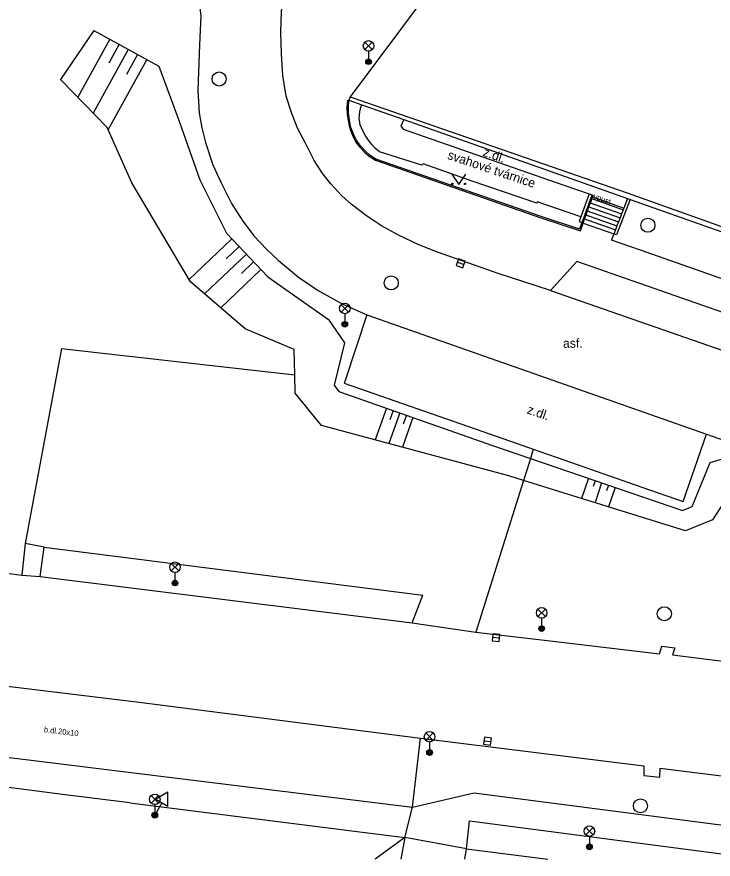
# Model space of a CAD drawing. Extents: x -598932 to -598196, y -1162207 to -1161504.
# Drawn here: x -598771.5 to -598721.9, y -1162207 to -1162147.1 of the extents above; entities that cross this region are included whole.
import ezdxf

# ---------------------------------------------------------------- set-up
doc = ezdxf.new("R2010")
doc.units = 0
for name, color, linetype in [('kanalizace - povrch.  znaky - skut. velikost', 7, 'Continuous'), ('Level 27', 7, 'Continuous'), ('Level 33', 7, 'Continuous'), ('Level 34', 7, 'Continuous'), ('Level 36', 7, 'Continuous'), ('specificka linie pasportu komunikaci', 7, 'Continuous'), ('TM - budovy zdene_ betonove - VP', 7, 'Continuous'), ('TM - chodniky - VP', 7, 'Continuous'), ('TM - dolni hrana svahu', 7, 'Continuous'), ('TM - horni hrana svahu', 7, 'Continuous'), ('TM - komunikace - VP', 7, 'Continuous'), ('TM - pomocna konstrukcna linie', 7, 'Continuous'), ('TM - popis povrchu', 7, 'Continuous'), ('TM - poznamka', 7, 'Continuous'), ('TM - rozhrani mezi zpev. plochami mezi sebou - VP', 7, 'Continuous'), ('TM - rozhrani ploch obecne - VP', 7, 'Continuous'), ('TM - schody - VP', 7, 'Continuous'), ('TM - srafovani', 7, 'Continuous'), ('TM - zabradli - VP', 7, 'Continuous')]:
    doc.layers.add(name, color=color, linetype=linetype)

msp = doc.modelspace()

# ---------------------------------------------------------------- linework, layer by layer
at = {"layer": 'kanalizace - povrch.  znaky - skut. velikost'}
for points in [[(-598730.65, -1162159.96), (-598728.35, -1162160.79)], [(-598730.61, -1162159.84), (-598730.52, -1162159.87)], [(-598730.52, -1162159.87), (-598728.31, -1162160.67)]]:
    msp.add_lwpolyline(points, dxfattribs=at)
at = {"layer": 'Level 27'}
for p, q in [((-598740.136, -1162164.518), (-598739.664, -1162164.682)), ((-598737.649, -1162191.185), (-598737.151, -1162191.235)), ((-598738.249, -1162198.545), (-598737.751, -1162198.595))]:
    msp.add_line(p, q, dxfattribs=at)
for points in [[(-598740.218, -1162164.754), (-598739.746, -1162164.918), (-598739.582, -1162164.446), (-598740.054, -1162164.282)], [(-598737.674, -1162191.433), (-598737.177, -1162191.484), (-598737.126, -1162190.987), (-598737.623, -1162190.936)], [(-598738.274, -1162198.793), (-598737.777, -1162198.844), (-598737.726, -1162198.347), (-598738.223, -1162198.296)]]:
    msp.add_lwpolyline(points, close=True, dxfattribs=at)
for centre in [(-598757.09, -1162151.49), (-598726.59, -1162161.89), (-598744.85, -1162165.99), (-598725.42, -1162189.51), (-598727.12, -1162203.17)]:
    msp.add_circle(centre, 0.5, dxfattribs=at)
at = {"layer": 'Level 33'}
for p, q in [((-598746.725, -1162149.4), (-598746.195, -1162148.87)), ((-598746.725, -1162148.87), (-598746.195, -1162149.4)), ((-598746.46, -1162149.51), (-598746.46, -1162150.26)), ((-598748.415, -1162168.07), (-598747.885, -1162167.54)), ((-598748.415, -1162167.54), (-598747.885, -1162168.07)), ((-598748.15, -1162168.18), (-598748.15, -1162168.93)), ((-598760.495, -1162186.47), (-598759.965, -1162185.94)), ((-598760.495, -1162185.94), (-598759.965, -1162186.47)), ((-598760.23, -1162186.58), (-598760.23, -1162187.33)), ((-598734.415, -1162189.71), (-598733.885, -1162189.18)), ((-598734.415, -1162189.18), (-598733.885, -1162189.71)), ((-598734.15, -1162189.82), (-598734.15, -1162190.57)), ((-598742.385, -1162198.52), (-598741.855, -1162197.99)), ((-598742.385, -1162197.99), (-598741.855, -1162198.52)), ((-598742.12, -1162198.63), (-598742.12, -1162199.38)), ((-598761.935, -1162202.97), (-598761.405, -1162202.44)), ((-598761.935, -1162202.44), (-598761.405, -1162202.97)), ((-598761.67, -1162203.08), (-598761.67, -1162203.83)), ((-598731.015, -1162205.23), (-598730.485, -1162204.7)), ((-598731.015, -1162204.7), (-598730.485, -1162205.23)), ((-598730.75, -1162205.34), (-598730.75, -1162206.09))]:
    msp.add_line(p, q, dxfattribs=at)
for centre, radius in [((-598746.46, -1162149.135), 0.375), ((-598746.46, -1162150.26), 0.2), ((-598746.46, -1162150.26), 0.145), ((-598746.46, -1162150.26), 0.0876), ((-598748.15, -1162167.805), 0.375), ((-598748.15, -1162168.93), 0.2), ((-598748.15, -1162168.93), 0.145), ((-598748.15, -1162168.93), 0.0876), ((-598760.23, -1162186.205), 0.375), ((-598760.23, -1162187.33), 0.2), ((-598760.23, -1162187.33), 0.145), ((-598760.23, -1162187.33), 0.0876), ((-598734.15, -1162189.445), 0.375), ((-598734.15, -1162190.57), 0.2), ((-598734.15, -1162190.57), 0.145), ((-598734.15, -1162190.57), 0.0876), ((-598742.12, -1162198.255), 0.375), ((-598742.12, -1162199.38), 0.2), ((-598742.12, -1162199.38), 0.145), ((-598742.12, -1162199.38), 0.0876), ((-598761.67, -1162202.705), 0.375), ((-598761.67, -1162203.83), 0.2), ((-598761.67, -1162203.83), 0.145), ((-598761.67, -1162203.83), 0.0876), ((-598730.75, -1162204.965), 0.375), ((-598730.75, -1162206.09), 0.2), ((-598730.75, -1162206.09), 0.145), ((-598730.75, -1162206.09), 0.0876)]:
    msp.add_circle(centre, radius, dxfattribs=at)
at = {"layer": 'Level 34'}
for p, q in [((-598761.163, -1162202.947), (-598761.67, -1162203.83)), ((-598761.887, -1162203.706), (-598761.453, -1162203.954))]:
    msp.add_line(p, q, dxfattribs=at)
msp.add_lwpolyline([(-598761.597, -1162202.698), (-598760.73, -1162203.196), (-598760.732, -1162202.196)], close=True, dxfattribs=at)
at = {"layer": 'Level 36'}
msp.add_lwpolyline([(-598740.54, -1162158.25), (-598740.04, -1162159), (-598739.54, -1162158.25)], dxfattribs=at)
for centre in [(-598740.49, -1162158.95), (-598739.591, -1162158.95)]:
    msp.add_circle(centre, 0.05, dxfattribs=at)
at = {"layer": 'specificka linie pasportu komunikaci'}
for points in [[(-598768.31, -1162170.66), (-598770.88, -1162184.51)], [(-598768.31, -1162170.66), (-598751.7, -1162172.52)], [(-598734.74, -1162177.81), (-598734.95, -1162178.48)], [(-598734.95, -1162178.48), (-598735.02, -1162178.72), (-598735.43, -1162180.03), (-598738.82, -1162190.81)], [(-598770.88, -1162184.51), (-598771.12, -1162186.77)], [(-598769.53, -1162184.78), (-598770.88, -1162184.51)], [(-598769.83, -1162186.86), (-598769.53, -1162184.78)], [(-598769.53, -1162184.78), (-598742.6, -1162188.19)], [(-598743.36, -1162190.15), (-598742.6, -1162188.19)], [(-598743.88, -1162205.42), (-598743.34, -1162203.26)], [(-598743.88, -1162205.42), (-598744.16, -1162206.96)], [(-598739.5, -1162206.22), (-598743.88, -1162205.42)]]:
    msp.add_lwpolyline(points, dxfattribs=at)
at = {"layer": 'TM - budovy zdene_ betonove - VP'}
for points in [[(-598728.07, -1162159.58), (-598700.55, -1162169.39), (-598688.31, -1162134.81)], [(-598733.44, -1162140.3), (-598735.12, -1162145.09), (-598740.6, -1162143.17), (-598747.78, -1162152.76)], [(-598747.78, -1162152.76), (-598728.07, -1162159.58)], [(-598739.603, -1162206.96), (-598739.5, -1162206.22)], [(-598739.5, -1162206.22), (-598733.697, -1162206.96)]]:
    msp.add_lwpolyline(points, dxfattribs=at)
at = {"layer": 'TM - chodniky - VP'}
for points in [[(-598731.28, -1162161.7), (-598731.45, -1162162.16), (-598734.18, -1162161.26), (-598745.94, -1162157.18), (-598746.36, -1162156.9), (-598746.73, -1162156.58), (-598747.05, -1162156.22), (-598747.31, -1162155.85), (-598747.53, -1162155.41), (-598747.71, -1162154.94), (-598747.82, -1162154.41), (-598747.88, -1162153.92), (-598747.89, -1162153.49), (-598747.86, -1162153)], [(-598747.78, -1162152.76), (-598747.86, -1162153)], [(-598747.86, -1162153), (-598746.94, -1162153.32)], [(-598731.35, -1162161.29), (-598734.47, -1162160.22), (-598734.5, -1162160.32), (-598739.16, -1162158.74), (-598742.57, -1162157.53), (-598742.68, -1162157.61), (-598745.69, -1162156.67), (-598745.96, -1162156.43), (-598746.24, -1162156.13), (-598746.52, -1162155.77), (-598746.71, -1162155.48), (-598746.87, -1162155.17), (-598747.05, -1162154.75), (-598747.12, -1162154.28), (-598747.08, -1162153.83), (-598746.98, -1162153.43), (-598746.94, -1162153.32)], [(-598746.94, -1162153.32), (-598743.94, -1162154.38)], [(-598743.94, -1162154.38), (-598728.04, -1162159.99)], [(-598728.04, -1162159.99), (-598728.31, -1162160.67)], [(-598728.04, -1162159.99), (-598727.85, -1162160.06)], [(-598727.85, -1162160.06), (-598710.85, -1162166.05)], [(-598728.35, -1162160.79), (-598728.46, -1162161.07)], [(-598728.31, -1162160.67), (-598728.35, -1162160.79)], [(-598731.35, -1162161.29), (-598731.47, -1162161.63), (-598731.28, -1162161.7)], [(-598728.57, -1162161.35), (-598728.68, -1162161.64)], [(-598728.46, -1162161.07), (-598728.57, -1162161.35)], [(-598728.79, -1162161.92), (-598728.9, -1162162.21)], [(-598728.68, -1162161.64), (-598728.79, -1162161.92)], [(-598729.01, -1162162.49), (-598729.18, -1162162.96)], [(-598728.9, -1162162.21), (-598729.01, -1162162.49)], [(-598710.85, -1162166.05), (-598711.92, -1162168.97), (-598717.68, -1162166.98), (-598727.11, -1162163.67), (-598729.18, -1162162.96)], [(-598763.45, -1162202.95), (-598768.41, -1162202.34), (-598772.43, -1162201.81)], [(-598743.34, -1162203.26), (-598738.95, -1162202.25)], [(-598738.95, -1162202.25), (-598702.604, -1162206.96)], [(-598763.45, -1162202.95), (-598743.88, -1162205.42)], [(-598739.5, -1162206.22), (-598739.28, -1162204.23), (-598718.442, -1162206.96)], [(-598743.88, -1162205.42), (-598745.996, -1162206.96)]]:
    msp.add_lwpolyline(points, dxfattribs=at)
at = {"layer": 'TM - dolni hrana svahu'}
msp.add_lwpolyline([(-598710.29, -1162184.81), (-598711.52, -1162182.65), (-598720.39, -1162180.35), (-598722, -1162182.84), (-598723.92, -1162183.61), (-598735.43, -1162180.03), (-598736.48, -1162179.7), (-598749.81, -1162176.12), (-598751.67, -1162173.82), (-598751.7, -1162172.52), (-598751.75, -1162170.72), (-598755.24, -1162169.25), (-598759.12, -1162165.91), (-598763.29, -1162158.88), (-598765.05, -1162154.94), (-598768.37, -1162151.53)], dxfattribs=at)
at = {"layer": 'TM - horni hrana svahu'}
for points in [[(-598766.01, -1162148.03), (-598761.39, -1162150.58), (-598759.9, -1162154.57), (-598758.47, -1162158.67), (-598756.57, -1162162.45), (-598753.63, -1162165.56), (-598749.3, -1162168.58), (-598748.17, -1162170.26), (-598748.9, -1162173.26), (-598748.58, -1162173.7), (-598737.64, -1162177.56), (-598734.95, -1162178.48)], [(-598734.95, -1162178.48), (-598724.14, -1162182.16), (-598723.43, -1162181.89), (-598722.15, -1162178.76), (-598720.89, -1162178.38), (-598710.84, -1162181.96), (-598710.29, -1162184.81)]]:
    msp.add_lwpolyline(points, dxfattribs=at)
at = {"layer": 'TM - komunikace - VP'}
for points in [[(-598758.64, -1162145.01), (-598758.55, -1162145.7), (-598758.4, -1162147), (-598758.48, -1162149.06), (-598758.61, -1162152.3), (-598758.5, -1162153.9), (-598758.32, -1162154.95), (-598758.07, -1162156.01), (-598757.54, -1162157.59), (-598756.98, -1162158.83), (-598756.22, -1162160.34), (-598755.4, -1162161.6), (-598754.59, -1162162.66), (-598753.75, -1162163.57), (-598752.86, -1162164.4), (-598751.44, -1162165.58), (-598750.04, -1162166.52), (-598748.33, -1162167.48), (-598746.58, -1162168.25)], [(-598737.25, -1162165.31), (-598741.56, -1162163.8), (-598742.89, -1162163.28), (-598744.33, -1162162.6), (-598745.53, -1162161.92), (-598746.6, -1162161.21), (-598747.7, -1162160.38), (-598748.35, -1162159.79), (-598749.15, -1162158.95), (-598749.72, -1162158.23), (-598750.32, -1162157.29), (-598750.93, -1162156.1), (-598751.51, -1162154.98), (-598751.93, -1162153.94), (-598752.31, -1162152.7), (-598752.55, -1162151.24), (-598752.65, -1162149.69), (-598752.71, -1162148.15), (-598752.66, -1162146.7), (-598752.54, -1162145.66)], [(-598704.24, -1162176.69), (-598704.55, -1162173.89), (-598704.6, -1162173.87), (-598711, -1162171.65), (-598718.19, -1162169.15), (-598731.64, -1162164.47), (-598733.52, -1162166.53)], [(-598733.52, -1162166.53), (-598737.25, -1162165.31)], [(-598746.58, -1162168.25), (-598748.13, -1162172.92), (-598748.2, -1162173.12), (-598738.88, -1162176.37), (-598737.45, -1162176.87), (-598735.9, -1162177.41), (-598734.74, -1162177.81), (-598732.58, -1162178.56), (-598727.02, -1162180.5), (-598724.08, -1162181.52), (-598722.41, -1162176.74)], [(-598722.41, -1162176.74), (-598712.86, -1162180.1)], [(-598772.19, -1162186.63), (-598771.12, -1162186.77), (-598769.83, -1162186.86), (-598743.36, -1162190.15)], [(-598743.36, -1162190.15), (-598738.82, -1162190.81), (-598733.14, -1162191.48)], [(-598733.14, -1162191.48), (-598725.77, -1162192.35), (-598725.6, -1162191.81), (-598724.67, -1162191.93), (-598724.84, -1162192.43), (-598699.38, -1162195.64), (-598688.04, -1162197.08), (-598673.19, -1162198.97)], [(-598743.34, -1162203.26), (-598742.76, -1162198.35)], [(-598742.76, -1162198.35), (-598737.22, -1162199.04)], [(-598737.22, -1162199.04), (-598726.89, -1162200.32), (-598726.88, -1162201.01), (-598725.74, -1162201.14), (-598725.72, -1162200.49), (-598689.52, -1162205.02), (-598681.7, -1162206)], [(-598773.38, -1162199.57), (-598743.34, -1162203.26)]]:
    msp.add_lwpolyline(points, dxfattribs=at)
at = {"layer": 'TM - pomocna konstrukcna linie'}
msp.add_lwpolyline([(-598766.01, -1162148.03), (-598768.37, -1162151.53)], dxfattribs=at)
at = {"layer": 'TM - rozhrani mezi zpev. plochami mezi sebou - VP'}
for points in [[(-598772.77, -1162194.58), (-598762.79, -1162195.8)], [(-598762.79, -1162195.8), (-598742.76, -1162198.35)]]:
    msp.add_lwpolyline(points, dxfattribs=at)
at = {"layer": 'TM - rozhrani ploch obecne - VP'}
for points in [[(-598743.94, -1162154.38), (-598744.16, -1162154.84), (-598744.01, -1162155.05), (-598732.58, -1162159.03), (-598730.76, -1162159.66), (-598730.569, -1162159.726)], [(-598730.76, -1162159.66), (-598731.35, -1162161.29)], [(-598730.76, -1162160.26), (-598730.87, -1162160.55)], [(-598730.65, -1162159.96), (-598730.76, -1162160.26)], [(-598730.76, -1162160.26), (-598728.46, -1162161.07)], [(-598730.61, -1162159.84), (-598730.65, -1162159.96)], [(-598730.569, -1162159.726), (-598730.61, -1162159.84)], [(-598727.85, -1162160.06), (-598728.82, -1162162.56), (-598729.01, -1162162.49)], [(-598730.97, -1162160.83), (-598731.07, -1162161.12)], [(-598730.87, -1162160.55), (-598730.97, -1162160.83)], [(-598731.18, -1162161.41), (-598731.28, -1162161.7)], [(-598731.07, -1162161.12), (-598731.18, -1162161.41)], [(-598731.28, -1162161.7), (-598731.19, -1162161.73)], [(-598731.19, -1162161.73), (-598729.01, -1162162.49)], [(-598733.52, -1162166.53), (-598712.19, -1162173.94), (-598704.24, -1162176.69)], [(-598746.58, -1162168.25), (-598722.41, -1162176.74)]]:
    msp.add_lwpolyline(points, dxfattribs=at)
at = {"layer": 'TM - schody - VP'}
for points in [[(-598730.97, -1162160.83), (-598728.68, -1162161.64)], [(-598730.87, -1162160.55), (-598728.57, -1162161.35)], [(-598731.18, -1162161.41), (-598728.9, -1162162.21)], [(-598731.07, -1162161.12), (-598728.79, -1162161.92)]]:
    msp.add_lwpolyline(points, dxfattribs=at)
at = {"layer": 'TM - srafovani'}
for points in [[(-598764.86, -1162148.66), (-598767.14, -1162152.79)], [(-598763.55, -1162149.39), (-598766.05, -1162153.92)], [(-598764.92, -1162150.33), (-598764.2, -1162149.03)], [(-598762.89, -1162149.75), (-598763.67, -1162151.17)], [(-598762.23, -1162150.11), (-598764.98, -1162155.09)], [(-598756.18, -1162162.86), (-598759.22, -1162165.74)], [(-598755.67, -1162163.41), (-598756.58, -1162164.27)], [(-598755.15, -1162163.95), (-598758.13, -1162166.76)], [(-598754.12, -1162165.04), (-598756.98, -1162167.75)], [(-598754.64, -1162164.5), (-598755.51, -1162165.32)], [(-598745.18, -1162174.9), (-598745.98, -1162177.15)], [(-598744.24, -1162175.23), (-598745.01, -1162177.41)], [(-598744.71, -1162175.07), (-598744.95, -1162175.73)], [(-598743.3, -1162175.56), (-598744.04, -1162177.67)], [(-598743.77, -1162175.4), (-598744, -1162176.04)], [(-598730.82, -1162179.88), (-598731.31, -1162181.31)], [(-598730.35, -1162180.05), (-598730.49, -1162180.47)], [(-598729.88, -1162180.21), (-598730.35, -1162181.61)], [(-598729.4, -1162180.37), (-598729.54, -1162180.78)], [(-598728.93, -1162180.53), (-598729.4, -1162181.91)]]:
    msp.add_lwpolyline(points, dxfattribs=at)
at = {"layer": 'TM - zabradli - VP'}
for points in [[(-598747.96, -1162152.99), (-598748, -1162153.51), (-598747.98, -1162154.01), (-598747.92, -1162154.42), (-598747.84, -1162154.83), (-598747.72, -1162155.21), (-598747.55, -1162155.61), (-598747.31, -1162156.04), (-598747.08, -1162156.34), (-598746.75, -1162156.7), (-598746.42, -1162156.98), (-598745.97, -1162157.27), (-598734.21, -1162161.35), (-598731.39, -1162162.28), (-598731.19, -1162161.73)], [(-598730.67, -1162160.29), (-598730.56, -1162159.99)], [(-598730.56, -1162159.99), (-598730.52, -1162159.87)], [(-598730.52, -1162159.87), (-598730.47, -1162159.73)], [(-598730.98, -1162161.15), (-598730.88, -1162160.86)], [(-598730.88, -1162160.86), (-598730.78, -1162160.58)], [(-598730.78, -1162160.58), (-598730.67, -1162160.29)], [(-598731.19, -1162161.73), (-598731.09, -1162161.44)], [(-598731.09, -1162161.44), (-598730.98, -1162161.15)]]:
    msp.add_lwpolyline(points, dxfattribs=at)

# ---------------------------------------------------------------- texts
at = {"layer": 'TM - popis povrchu'}
for s, height, rotation, p in [('z.dl.', 0.65, 340.80155, (-598738.38, -1162156.94)), ('svahové tvárnice', 0.65, 341.27047, (-598740.9, -1162157.15)), ('z.dl.', 0.65, 340.82265, (-598735.24, -1162175.25)), ('b.dl.20x10', 0.4, 353.01121, (-598769.57, -1162197.93))]:
    msp.add_text(s, height=height, rotation=rotation, dxfattribs=at).set_placement(p)
msp.add_text('asf.', height=0.65, dxfattribs=at).set_placement((-598732.63, -1162170.6))
at = {"layer": 'TM - poznamka'}
msp.add_text('vpust', height=0.4, rotation=340, dxfattribs=at).set_placement((-598730.51, -1162159.98))

doc.saveas('drawing.dxf')
